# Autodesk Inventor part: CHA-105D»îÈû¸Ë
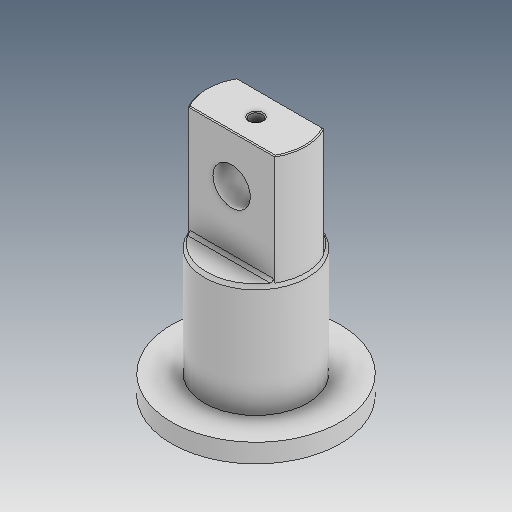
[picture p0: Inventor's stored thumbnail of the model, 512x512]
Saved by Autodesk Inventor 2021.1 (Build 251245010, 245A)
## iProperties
Created: 2019-12
Part Number: CHA-105D»îÈû¸Ë
Material: Ogólny
Document SubType Name: Modeling
Designer: user
Density: 1 g/cm^3
Appearance: Domyślna
Author: user
Revision Number: ÈÎºÎ
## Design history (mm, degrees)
feature "ÊäÈë1"
node "Bryła1"
